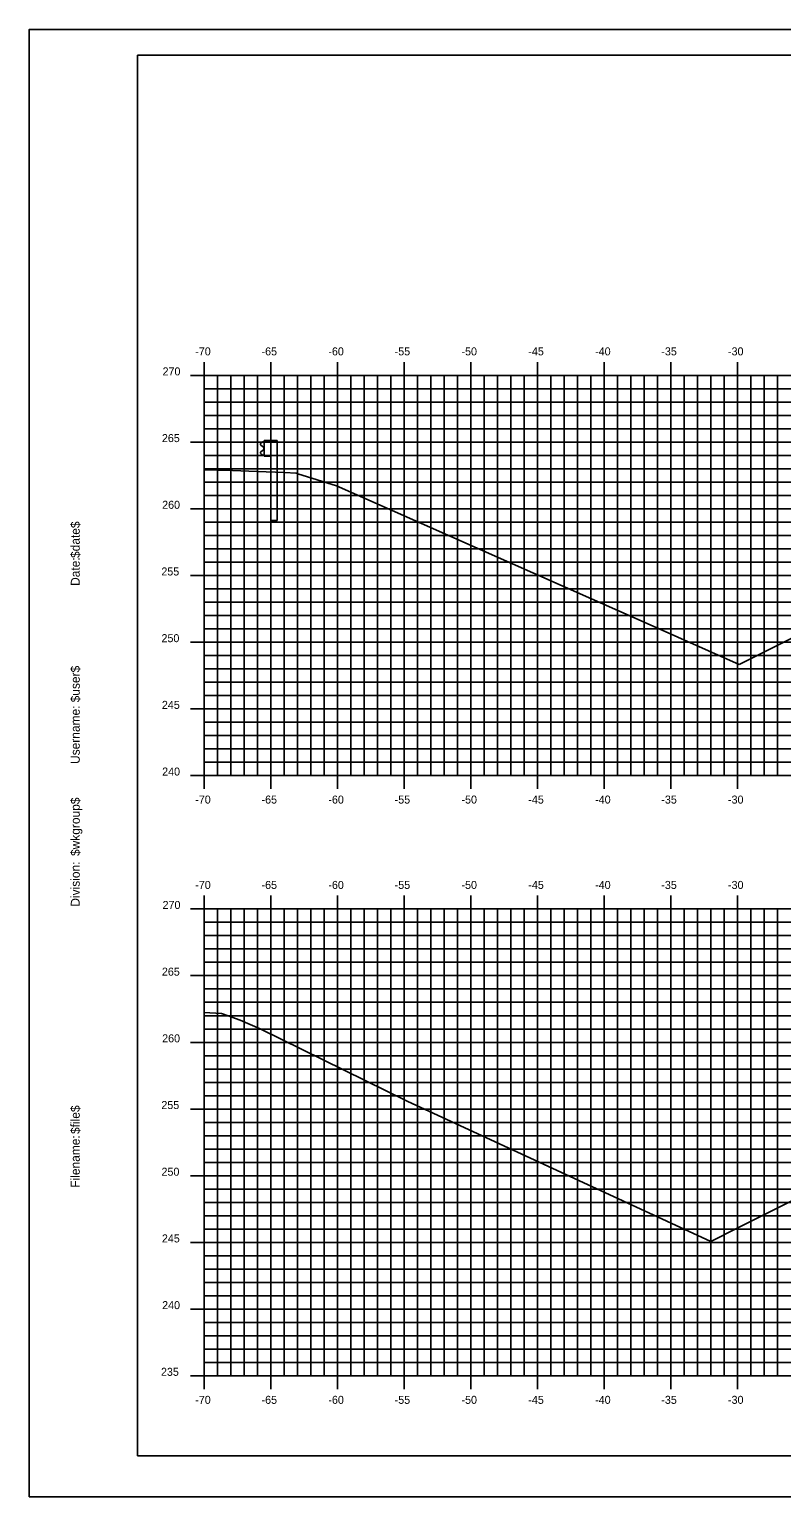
# Model space of a CAD drawing. Extents: x 1168600 to 1177589, y 610178 to 611246.
# Drawn here: x 1175422 to 1175478.4, y 610268.7 to 610378.7 of the extents above; entities that cross this region are included whole.
import ezdxf

# ---------------------------------------------------------------- set-up
doc = ezdxf.new("R2010")
doc.units = 0
for name, color, linetype in [('_Station Equation', 7, 'Continuous'), ('BORDER', 7, 'Continuous'), ('D_Slope_Fill', 7, 'Continuous'), ('D_Text_Standard', 7, 'Continuous'), ('H_V ANNOTATION', 7, 'Continuous'), ('MAJOR', 7, 'Continuous'), ('MINOR', 7, 'Continuous'), ('PLOT BOUNDARY', 7, 'Continuous')]:
    doc.layers.add(name, color=color, linetype=linetype)

msp = doc.modelspace()

# ---------------------------------------------------------------- linework, layer by layer
at = {"layer": '_Station Equation'}
for points in [[(1175435.12, 610345.72), (1175437.26, 610345.66), (1175439.11, 610345.59), (1175441.15, 610345.51), (1175442.03, 610345.47), (1175442.15, 610345.43), (1175445.05, 610344.51), (1175468.33, 610334.2), (1175475.23, 610331.13)], [(1175435.12, 610305.03), (1175436.43, 610304.97), (1175436.92, 610304.8), (1175437.82, 610304.47), (1175439.32, 610303.82), (1175450.35, 610298.38), (1175473.1, 610287.88)]]:
    msp.add_lwpolyline(points, dxfattribs=at)
at = {"layer": 'BORDER'}
for p, q in [((1175590.12, 610376.8), (1175430.12, 610376.8)), ((1175430.12, 610376.8), (1175430.12, 610271.8)), ((1175430.12, 610271.8), (1175590.12, 610271.8))]:
    msp.add_line(p, q, dxfattribs=at)
at = {"layer": 'D_Slope_Fill'}
for p, q in [((1175439.53, 610347.81), (1175439.38, 610347.71)), ((1175439.38, 610347.57), (1175439.58, 610347.43)), ((1175439.58, 610347.21), (1175439.38, 610347.08)), ((1175439.63, 610347.83), (1175439.54, 610347.82)), ((1175439.61, 610347.37), (1175439.61, 610347.28)), ((1175439.63, 610347.91), (1175440.12, 610347.91)), ((1175439.63, 610346.74), (1175439.63, 610347.91)), ((1175440.12, 610347.91), (1175440.61, 610347.91)), ((1175440.12, 610347.91), (1175440.12, 610346.74)), ((1175440.61, 610347.91), (1175440.61, 610341.91)), ((1175439.38, 610346.93), (1175439.53, 610346.83)), ((1175439.54, 610346.83), (1175439.63, 610346.81)), ((1175440.12, 610346.74), (1175439.63, 610346.74)), ((1175440.12, 610341.91), (1175440.12, 610346.74)), ((1175440.12, 610341.91), (1175440.61, 610341.91))]:
    msp.add_line(p, q, dxfattribs=at)
for centre, major_axis, start_param, end_param in [((1175439.43, 610347.64), (-0.0877, 0), 5.323254, 7.243116), ((1175439.55, 610347.78), (-0.0417, 0), 4.886922, 5.323254), ((1175439.53, 610347.37), (0.0789, 0), 0, 0.959931), ((1175439.53, 610347.28), (0.0789, 0), 5.323254, 6.283185), ((1175439.43, 610347.01), (-0.0877, 0), 5.323254, 7.243116), ((1175439.55, 610346.87), (-0.0417, 0), 0.959931, 1.396263)]:
    msp.add_ellipse(centre, major_axis=major_axis, ratio=0.995501, start_param=start_param, end_param=end_param, dxfattribs=at)
at = {"layer": 'D_Text_Standard'}
for points in [[(1175475.23, 610331.13), (1175482.58, 610334.81), (1175486.12, 610336.58), (1175489.12, 610336.7), (1175505.12, 610337.34), (1175521.12, 610337.98), (1175524.12, 610337.92), (1175528.08, 610335.94)], [(1175473.1, 610287.88), (1175475.03, 610288.84), (1175482.58, 610292.62), (1175486.12, 610294.38), (1175489.12, 610294.5), (1175505.12, 610295.14), (1175521.12, 610295.78), (1175524.12, 610295.72), (1175525.81, 610294.88)]]:
    msp.add_lwpolyline(points, dxfattribs=at)
at = {"layer": 'MAJOR'}
for p, q in [((1175435.12, 610353.8), (1175435.12, 610352.8)), ((1175440.12, 610353.8), (1175440.12, 610352.8)), ((1175445.12, 610353.8), (1175445.12, 610352.8)), ((1175450.12, 610353.8), (1175450.12, 610352.8)), ((1175455.12, 610353.8), (1175455.12, 610352.8)), ((1175460.12, 610353.8), (1175460.12, 610352.8)), ((1175465.12, 610353.8), (1175465.12, 610352.8)), ((1175470.12, 610353.8), (1175470.12, 610352.8)), ((1175475.12, 610353.8), (1175475.12, 610352.8)), ((1175434.11, 610352.8), (1175435.12, 610352.8)), ((1175435.12, 610352.8), (1175575.12, 610352.8)), ((1175435.12, 610322.8), (1175435.12, 610352.8)), ((1175435.12, 610322.8), (1175435.12, 610352.8)), ((1175435.12, 610352.8), (1175575.12, 610352.8)), ((1175440.12, 610322.8), (1175440.12, 610352.8)), ((1175445.12, 610322.8), (1175445.12, 610352.8)), ((1175450.12, 610322.8), (1175450.12, 610352.8)), ((1175455.12, 610322.8), (1175455.12, 610352.8)), ((1175460.12, 610322.8), (1175460.12, 610352.8)), ((1175465.12, 610322.8), (1175465.12, 610352.8)), ((1175470.12, 610322.8), (1175470.12, 610352.8)), ((1175475.12, 610322.8), (1175475.12, 610352.8)), ((1175434.11, 610347.8), (1175435.12, 610347.8)), ((1175435.12, 610347.8), (1175575.12, 610347.8)), ((1175434.11, 610342.8), (1175435.12, 610342.8)), ((1175435.12, 610342.8), (1175575.12, 610342.8)), ((1175434.11, 610337.8), (1175435.12, 610337.8)), ((1175435.12, 610337.8), (1175575.12, 610337.8)), ((1175434.11, 610332.8), (1175435.12, 610332.8)), ((1175435.12, 610332.8), (1175575.12, 610332.8)), ((1175434.11, 610327.8), (1175435.12, 610327.8)), ((1175435.12, 610327.8), (1175575.12, 610327.8)), ((1175434.11, 610322.8), (1175435.12, 610322.8)), ((1175435.12, 610322.8), (1175575.12, 610322.8)), ((1175435.12, 610322.8), (1175575.12, 610322.8)), ((1175435.12, 610321.8), (1175435.12, 610322.8)), ((1175440.12, 610321.8), (1175440.12, 610322.8)), ((1175445.12, 610321.8), (1175445.12, 610322.8)), ((1175450.12, 610321.8), (1175450.12, 610322.8)), ((1175455.12, 610321.8), (1175455.12, 610322.8)), ((1175460.12, 610321.8), (1175460.12, 610322.8)), ((1175465.12, 610321.8), (1175465.12, 610322.8)), ((1175470.12, 610321.8), (1175470.12, 610322.8)), ((1175475.12, 610321.8), (1175475.12, 610322.8)), ((1175435.12, 610313.8), (1175435.12, 610312.8)), ((1175440.12, 610313.8), (1175440.12, 610312.8)), ((1175445.12, 610313.8), (1175445.12, 610312.8)), ((1175450.12, 610313.8), (1175450.12, 610312.8)), ((1175455.12, 610313.8), (1175455.12, 610312.8)), ((1175460.12, 610313.8), (1175460.12, 610312.8)), ((1175465.12, 610313.8), (1175465.12, 610312.8)), ((1175470.12, 610313.8), (1175470.12, 610312.8)), ((1175475.12, 610313.8), (1175475.12, 610312.8)), ((1175434.11, 610312.8), (1175435.12, 610312.8)), ((1175435.12, 610312.8), (1175575.12, 610312.8)), ((1175435.12, 610277.8), (1175435.12, 610312.8)), ((1175435.12, 610277.8), (1175435.12, 610312.8)), ((1175435.12, 610312.8), (1175575.12, 610312.8)), ((1175440.12, 610277.8), (1175440.12, 610312.8)), ((1175445.12, 610277.8), (1175445.12, 610312.8)), ((1175450.12, 610277.8), (1175450.12, 610312.8)), ((1175455.12, 610277.8), (1175455.12, 610312.8)), ((1175460.12, 610277.8), (1175460.12, 610312.8)), ((1175465.12, 610277.8), (1175465.12, 610312.8)), ((1175470.12, 610277.8), (1175470.12, 610312.8)), ((1175475.12, 610277.8), (1175475.12, 610312.8)), ((1175434.11, 610307.8), (1175435.12, 610307.8)), ((1175435.12, 610307.8), (1175575.12, 610307.8)), ((1175434.11, 610302.8), (1175435.12, 610302.8)), ((1175435.12, 610302.8), (1175575.12, 610302.8)), ((1175434.11, 610297.8), (1175435.12, 610297.8)), ((1175435.12, 610297.8), (1175575.12, 610297.8)), ((1175434.11, 610292.8), (1175435.12, 610292.8)), ((1175435.12, 610292.8), (1175575.12, 610292.8)), ((1175434.11, 610287.8), (1175435.12, 610287.8)), ((1175435.12, 610287.8), (1175575.12, 610287.8)), ((1175434.11, 610282.8), (1175435.12, 610282.8)), ((1175435.12, 610282.8), (1175575.12, 610282.8)), ((1175434.11, 610277.8), (1175435.12, 610277.8)), ((1175435.12, 610277.8), (1175575.12, 610277.8)), ((1175435.12, 610277.8), (1175575.12, 610277.8)), ((1175435.12, 610276.8), (1175435.12, 610277.8)), ((1175440.12, 610276.8), (1175440.12, 610277.8)), ((1175445.12, 610276.8), (1175445.12, 610277.8)), ((1175450.12, 610276.8), (1175450.12, 610277.8)), ((1175455.12, 610276.8), (1175455.12, 610277.8)), ((1175460.12, 610276.8), (1175460.12, 610277.8)), ((1175465.12, 610276.8), (1175465.12, 610277.8)), ((1175470.12, 610276.8), (1175470.12, 610277.8)), ((1175475.12, 610276.8), (1175475.12, 610277.8))]:
    msp.add_line(p, q, dxfattribs=at)
at = {"layer": 'MINOR'}
for p, q in [((1175436.12, 610322.8), (1175436.12, 610352.8)), ((1175437.12, 610322.8), (1175437.12, 610352.8)), ((1175438.12, 610322.8), (1175438.12, 610352.8)), ((1175439.12, 610322.8), (1175439.12, 610352.8)), ((1175441.12, 610322.8), (1175441.12, 610352.8)), ((1175442.12, 610322.8), (1175442.12, 610352.8)), ((1175443.12, 610322.8), (1175443.12, 610352.8)), ((1175444.12, 610322.8), (1175444.12, 610352.8)), ((1175446.12, 610322.8), (1175446.12, 610352.8)), ((1175447.12, 610322.8), (1175447.12, 610352.8)), ((1175448.12, 610322.8), (1175448.12, 610352.8)), ((1175449.12, 610322.8), (1175449.12, 610352.8)), ((1175451.12, 610322.8), (1175451.12, 610352.8)), ((1175452.12, 610322.8), (1175452.12, 610352.8)), ((1175453.12, 610322.8), (1175453.12, 610352.8)), ((1175454.12, 610322.8), (1175454.12, 610352.8)), ((1175456.12, 610322.8), (1175456.12, 610352.8)), ((1175457.12, 610322.8), (1175457.12, 610352.8)), ((1175458.12, 610322.8), (1175458.12, 610352.8)), ((1175459.12, 610322.8), (1175459.12, 610352.8)), ((1175461.12, 610322.8), (1175461.12, 610352.8)), ((1175462.12, 610322.8), (1175462.12, 610352.8)), ((1175463.12, 610322.8), (1175463.12, 610352.8)), ((1175464.12, 610322.8), (1175464.12, 610352.8)), ((1175466.12, 610322.8), (1175466.12, 610352.8)), ((1175467.12, 610322.8), (1175467.12, 610352.8)), ((1175468.12, 610322.8), (1175468.12, 610352.8)), ((1175469.12, 610322.8), (1175469.12, 610352.8)), ((1175471.12, 610322.8), (1175471.12, 610352.8)), ((1175472.12, 610322.8), (1175472.12, 610352.8)), ((1175473.12, 610322.8), (1175473.12, 610352.8)), ((1175474.12, 610322.8), (1175474.12, 610352.8)), ((1175476.12, 610322.8), (1175476.12, 610352.8)), ((1175477.12, 610322.8), (1175477.12, 610352.8)), ((1175478.12, 610322.8), (1175478.12, 610352.8)), ((1175435.12, 610351.8), (1175575.12, 610351.8)), ((1175435.12, 610351.8), (1175436.12, 610351.8)), ((1175435.12, 610350.8), (1175575.12, 610350.8)), ((1175435.12, 610350.8), (1175436.12, 610350.8)), ((1175435.12, 610349.8), (1175575.12, 610349.8)), ((1175435.12, 610349.8), (1175436.12, 610349.8)), ((1175435.12, 610348.8), (1175575.12, 610348.8)), ((1175435.12, 610348.8), (1175436.12, 610348.8)), ((1175435.12, 610346.8), (1175575.12, 610346.8)), ((1175435.12, 610346.8), (1175436.12, 610346.8)), ((1175435.12, 610345.8), (1175575.12, 610345.8)), ((1175435.12, 610345.8), (1175436.12, 610345.8)), ((1175435.12, 610344.8), (1175575.12, 610344.8)), ((1175435.12, 610344.8), (1175436.12, 610344.8)), ((1175435.12, 610343.8), (1175575.12, 610343.8)), ((1175435.12, 610343.8), (1175436.12, 610343.8)), ((1175435.12, 610341.8), (1175575.12, 610341.8)), ((1175435.12, 610341.8), (1175436.12, 610341.8)), ((1175435.12, 610340.8), (1175575.12, 610340.8)), ((1175435.12, 610340.8), (1175436.12, 610340.8)), ((1175435.12, 610339.8), (1175575.12, 610339.8)), ((1175435.12, 610339.8), (1175436.12, 610339.8)), ((1175435.12, 610338.8), (1175575.12, 610338.8)), ((1175435.12, 610338.8), (1175436.12, 610338.8)), ((1175435.12, 610336.8), (1175575.12, 610336.8)), ((1175435.12, 610336.8), (1175436.12, 610336.8)), ((1175435.12, 610335.8), (1175575.12, 610335.8)), ((1175435.12, 610335.8), (1175436.12, 610335.8)), ((1175435.12, 610334.8), (1175575.12, 610334.8)), ((1175435.12, 610334.8), (1175436.12, 610334.8)), ((1175435.12, 610333.8), (1175575.12, 610333.8)), ((1175435.12, 610333.8), (1175436.12, 610333.8)), ((1175435.12, 610331.8), (1175575.12, 610331.8)), ((1175435.12, 610331.8), (1175436.12, 610331.8)), ((1175435.12, 610330.8), (1175575.12, 610330.8)), ((1175435.12, 610330.8), (1175436.12, 610330.8)), ((1175435.12, 610329.8), (1175575.12, 610329.8)), ((1175435.12, 610329.8), (1175436.12, 610329.8)), ((1175435.12, 610328.8), (1175575.12, 610328.8)), ((1175435.12, 610328.8), (1175436.12, 610328.8)), ((1175435.12, 610326.8), (1175575.12, 610326.8)), ((1175435.12, 610326.8), (1175436.12, 610326.8)), ((1175435.12, 610325.8), (1175575.12, 610325.8)), ((1175435.12, 610325.8), (1175436.12, 610325.8)), ((1175435.12, 610324.8), (1175575.12, 610324.8)), ((1175435.12, 610324.8), (1175436.12, 610324.8)), ((1175435.12, 610323.8), (1175575.12, 610323.8)), ((1175435.12, 610323.8), (1175436.12, 610323.8)), ((1175436.12, 610277.8), (1175436.12, 610312.8)), ((1175437.12, 610277.8), (1175437.12, 610312.8)), ((1175438.12, 610277.8), (1175438.12, 610312.8)), ((1175439.12, 610277.8), (1175439.12, 610312.8)), ((1175441.12, 610277.8), (1175441.12, 610312.8)), ((1175442.12, 610277.8), (1175442.12, 610312.8)), ((1175443.12, 610277.8), (1175443.12, 610312.8)), ((1175444.12, 610277.8), (1175444.12, 610312.8)), ((1175446.12, 610277.8), (1175446.12, 610312.8)), ((1175447.12, 610277.8), (1175447.12, 610312.8)), ((1175448.12, 610277.8), (1175448.12, 610312.8)), ((1175449.12, 610277.8), (1175449.12, 610312.8)), ((1175451.12, 610277.8), (1175451.12, 610312.8)), ((1175452.12, 610277.8), (1175452.12, 610312.8)), ((1175453.12, 610277.8), (1175453.12, 610312.8)), ((1175454.12, 610277.8), (1175454.12, 610312.8)), ((1175456.12, 610277.8), (1175456.12, 610312.8)), ((1175457.12, 610277.8), (1175457.12, 610312.8)), ((1175458.12, 610277.8), (1175458.12, 610312.8)), ((1175459.12, 610277.8), (1175459.12, 610312.8)), ((1175461.12, 610277.8), (1175461.12, 610312.8)), ((1175462.12, 610277.8), (1175462.12, 610312.8)), ((1175463.12, 610277.8), (1175463.12, 610312.8)), ((1175464.12, 610277.8), (1175464.12, 610312.8)), ((1175466.12, 610277.8), (1175466.12, 610312.8)), ((1175467.12, 610277.8), (1175467.12, 610312.8)), ((1175468.12, 610277.8), (1175468.12, 610312.8)), ((1175469.12, 610277.8), (1175469.12, 610312.8)), ((1175471.12, 610277.8), (1175471.12, 610312.8)), ((1175472.12, 610277.8), (1175472.12, 610312.8)), ((1175473.12, 610277.8), (1175473.12, 610312.8)), ((1175474.12, 610277.8), (1175474.12, 610312.8)), ((1175476.12, 610277.8), (1175476.12, 610312.8)), ((1175477.12, 610277.8), (1175477.12, 610312.8)), ((1175478.12, 610277.8), (1175478.12, 610312.8)), ((1175435.12, 610311.8), (1175575.12, 610311.8)), ((1175435.12, 610311.8), (1175436.12, 610311.8)), ((1175435.12, 610310.8), (1175575.12, 610310.8)), ((1175435.12, 610310.8), (1175436.12, 610310.8)), ((1175435.12, 610309.8), (1175575.12, 610309.8)), ((1175435.12, 610309.8), (1175436.12, 610309.8)), ((1175435.12, 610308.8), (1175575.12, 610308.8)), ((1175435.12, 610308.8), (1175436.12, 610308.8)), ((1175435.12, 610306.8), (1175575.12, 610306.8)), ((1175435.12, 610306.8), (1175436.12, 610306.8)), ((1175435.12, 610305.8), (1175575.12, 610305.8)), ((1175435.12, 610305.8), (1175436.12, 610305.8)), ((1175435.12, 610304.8), (1175575.12, 610304.8)), ((1175435.12, 610304.8), (1175436.12, 610304.8)), ((1175435.12, 610303.8), (1175575.12, 610303.8)), ((1175435.12, 610303.8), (1175436.12, 610303.8)), ((1175435.12, 610301.8), (1175575.12, 610301.8)), ((1175435.12, 610301.8), (1175436.12, 610301.8)), ((1175435.12, 610300.8), (1175575.12, 610300.8)), ((1175435.12, 610300.8), (1175436.12, 610300.8)), ((1175435.12, 610299.8), (1175575.12, 610299.8)), ((1175435.12, 610299.8), (1175436.12, 610299.8)), ((1175435.12, 610298.8), (1175575.12, 610298.8)), ((1175435.12, 610298.8), (1175436.12, 610298.8)), ((1175435.12, 610296.8), (1175575.12, 610296.8)), ((1175435.12, 610296.8), (1175436.12, 610296.8)), ((1175435.12, 610295.8), (1175575.12, 610295.8)), ((1175435.12, 610295.8), (1175436.12, 610295.8)), ((1175435.12, 610294.8), (1175575.12, 610294.8)), ((1175435.12, 610294.8), (1175436.12, 610294.8)), ((1175435.12, 610293.8), (1175575.12, 610293.8)), ((1175435.12, 610293.8), (1175436.12, 610293.8)), ((1175435.12, 610291.8), (1175575.12, 610291.8)), ((1175435.12, 610291.8), (1175436.12, 610291.8)), ((1175435.12, 610290.8), (1175575.12, 610290.8)), ((1175435.12, 610290.8), (1175436.12, 610290.8)), ((1175435.12, 610289.8), (1175575.12, 610289.8)), ((1175435.12, 610289.8), (1175436.12, 610289.8)), ((1175435.12, 610288.8), (1175575.12, 610288.8)), ((1175435.12, 610288.8), (1175436.12, 610288.8)), ((1175435.12, 610286.8), (1175575.12, 610286.8)), ((1175435.12, 610286.8), (1175436.12, 610286.8)), ((1175435.12, 610285.8), (1175575.12, 610285.8)), ((1175435.12, 610285.8), (1175436.12, 610285.8)), ((1175435.12, 610284.8), (1175575.12, 610284.8)), ((1175435.12, 610284.8), (1175436.12, 610284.8)), ((1175435.12, 610283.8), (1175575.12, 610283.8)), ((1175435.12, 610283.8), (1175436.12, 610283.8)), ((1175435.12, 610281.8), (1175575.12, 610281.8)), ((1175435.12, 610281.8), (1175436.12, 610281.8)), ((1175435.12, 610280.8), (1175575.12, 610280.8)), ((1175435.12, 610280.8), (1175436.12, 610280.8)), ((1175435.12, 610279.8), (1175575.12, 610279.8)), ((1175435.12, 610279.8), (1175436.12, 610279.8)), ((1175435.12, 610278.8), (1175575.12, 610278.8)), ((1175435.12, 610278.8), (1175436.12, 610278.8))]:
    msp.add_line(p, q, dxfattribs=at)
at = {"layer": 'PLOT BOUNDARY'}
msp.add_lwpolyline([(1175422.02, 610268.74), (1175592.02, 610268.74), (1175592.02, 610378.74), (1175422.02, 610378.74)], close=True, dxfattribs=at)

# ---------------------------------------------------------------- texts
at = {"layer": 'BORDER'}
for s, p in [('$date$', (1175425.8, 610339.11)), ('Date:', (1175425.8, 610337.02)), ('$user$', (1175425.8, 610328.29)), ('Username:', (1175425.8, 610323.67)), ('$wkgroup$', (1175425.8, 610316.77)), ('Division:', (1175425.8, 610312.97)), ('$file$', (1175425.8, 610295.93)), ('Filename:', (1175425.8, 610291.9))]:
    msp.add_text(s, height=0.67, rotation=90, dxfattribs=at).set_placement(p)
at = {"layer": 'H_V ANNOTATION'}
for s, p in [('-70', (1175434.46, 610354.3)), ('-65', (1175439.43, 610354.3)), ('-60', (1175444.44, 610354.3)), ('-55', (1175449.41, 610354.3)), ('-50', (1175454.42, 610354.3)), ('-45', (1175459.43, 610354.3)), ('-40', (1175464.44, 610354.3)), ('-35', (1175469.4, 610354.3)), ('-30', (1175474.4, 610354.3)), ('270', (1175432.01, 610352.8)), ('265', (1175431.96, 610347.8)), ('260', (1175431.98, 610342.8)), ('255', (1175431.92, 610337.8)), ('250', (1175431.93, 610332.8)), ('245', (1175431.96, 610327.8)), ('240', (1175431.98, 610322.8)), ('-70', (1175434.46, 610320.7)), ('-65', (1175439.43, 610320.7)), ('-60', (1175444.44, 610320.7)), ('-55', (1175449.41, 610320.7)), ('-50', (1175454.42, 610320.7)), ('-45', (1175459.43, 610320.7)), ('-40', (1175464.44, 610320.7)), ('-35', (1175469.4, 610320.7)), ('-30', (1175474.4, 610320.7)), ('-70', (1175434.46, 610314.3)), ('-65', (1175439.43, 610314.3)), ('-60', (1175444.44, 610314.3)), ('-55', (1175449.41, 610314.3)), ('-50', (1175454.42, 610314.3)), ('-45', (1175459.43, 610314.3)), ('-40', (1175464.44, 610314.3)), ('-35', (1175469.4, 610314.3)), ('-30', (1175474.4, 610314.3)), ('270', (1175432.01, 610312.8)), ('265', (1175431.96, 610307.8)), ('260', (1175431.98, 610302.8)), ('255', (1175431.92, 610297.8)), ('250', (1175431.93, 610292.8)), ('245', (1175431.96, 610287.8)), ('240', (1175431.98, 610282.8)), ('235', (1175431.89, 610277.8)), ('-70', (1175434.46, 610275.7)), ('-65', (1175439.43, 610275.7)), ('-60', (1175444.44, 610275.7)), ('-55', (1175449.41, 610275.7)), ('-50', (1175454.42, 610275.7)), ('-45', (1175459.43, 610275.7)), ('-40', (1175464.44, 610275.7)), ('-35', (1175469.4, 610275.7)), ('-30', (1175474.4, 610275.7))]:
    msp.add_text(s, height=0.6, dxfattribs=at).set_placement(p)

doc.saveas('drawing.dxf')
